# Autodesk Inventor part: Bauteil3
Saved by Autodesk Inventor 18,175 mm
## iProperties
Created: 2011-07
Part Number: Bauteil3
Material: S355J2+N(Cu<0,4%)
Document SubType Name: Blech
Density: 7.85 g/cm^3
Sheet Metal Rule: Standard
Flat Pattern Width: 1.81754 cm
Flat Pattern Length: 2.81581 cm
Flat Pattern Area: 5.11787 cm^2
Sheet Metal Width: 28,158 mm
Sheet Metal Length: 511,787 mm^2
MatBom2.0.1.: PS!Inventor!PV!14.0  SP: 3!AVMa!2!AVMi!0!AVBu!0
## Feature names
1. Extrusion1
2. Extrusion2
3. Grobblech1
4. Grobblech2
5. Biegung1
6. Grobblech3
7. Biegung2
